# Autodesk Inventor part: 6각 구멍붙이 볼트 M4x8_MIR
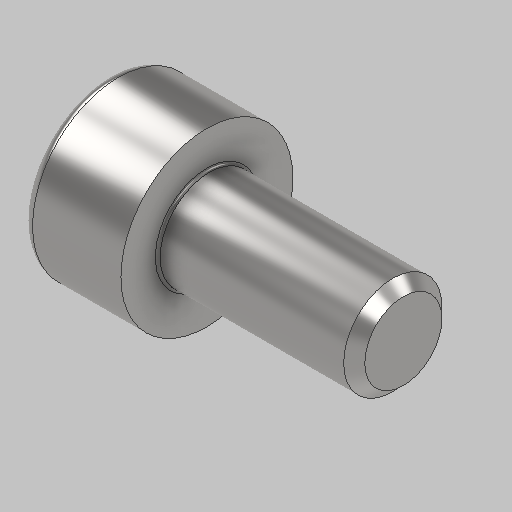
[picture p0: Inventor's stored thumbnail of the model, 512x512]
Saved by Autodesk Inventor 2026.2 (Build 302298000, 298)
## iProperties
Created: 2026-06
Part Number: 6각 구멍붙이 볼트 M4x8_MIR
Material: 강철, 연강
Description: 6각머리 태핑 나사
Document SubType Name: Modeling
Designer: sec7
Density: 7.85 g/cm^3
Appearance: 기본값
Author: jhkim
Sending System: Autodesk Inventor 2027
Preprocessor: ST-DEVELOPER v20.1
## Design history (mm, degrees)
derived "6각 구멍붙이 볼트 M4x8.ipt"
feature "솔리드1::6각 구멍붙이 볼트 M4x8.ipt" dims "d0" = 10
tag "피쳐 태그1"
node "솔리드1"
